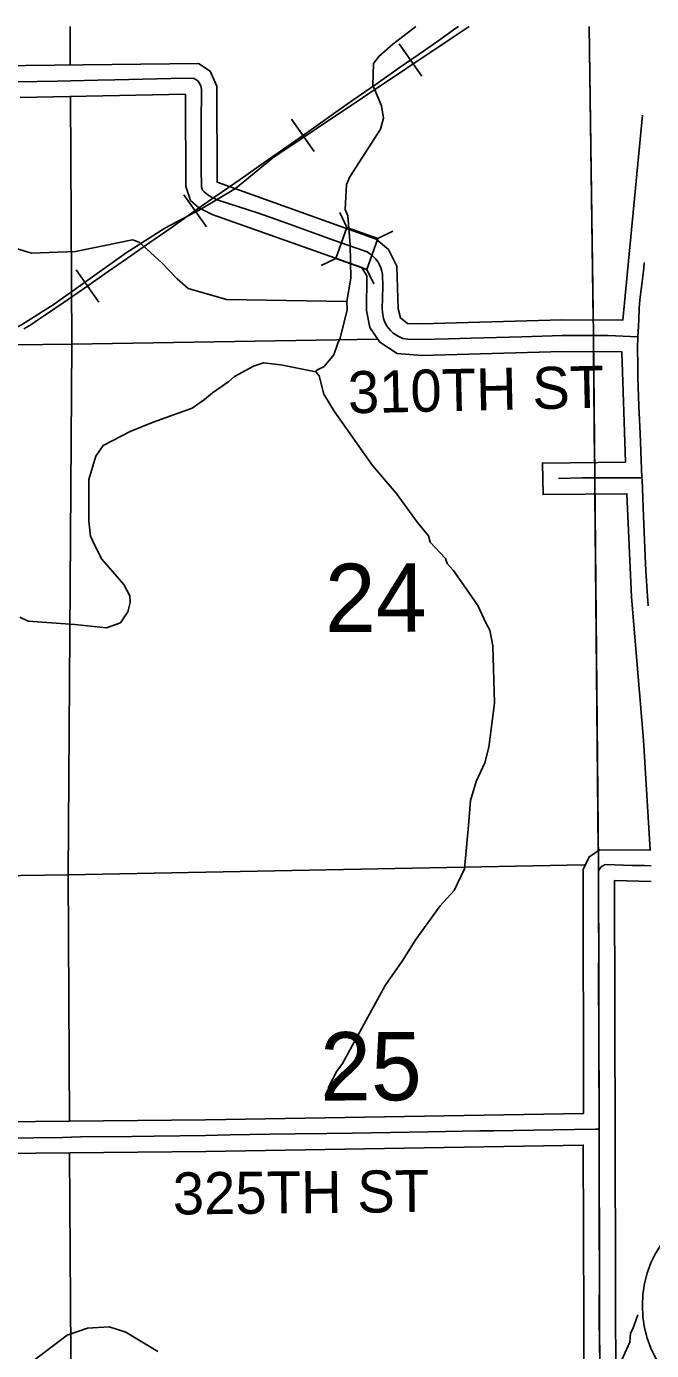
# Model space of a CAD drawing. Extents: x 10133 to 81668, y 7924 to 11018.
# Drawn here: x 12044.1 to 12222.4, y 9217.2 to 9594.9 of the extents above; entities that cross this region are included whole.
import ezdxf

# ---------------------------------------------------------------- set-up
doc = ezdxf.new("R2010")
doc.units = 0
for name, color, linetype in [('tdCoCityStreetMinor', 7, 'Continuous'), ('tdCoHydroRiver', 7, 'Continuous'), ('tdCoPriNonDiv', 7, 'Continuous'), ('tdCoRRCL', 7, 'Continuous'), ('tdCoRROwnerTxt', 7, 'Continuous'), ('tdCoShieldCoRte', 7, 'Continuous'), ('tdCoShieldCoRteHrd', 7, 'Continuous'), ('tdCoShieldStRte', 7, 'Continuous'), ('tdCoStrucNonDivPri', 7, 'Continuous'), ('tdCoSurfConc', 7, 'Continuous'), ('tdCoTwpNameTxt', 7, 'Continuous')]:
    doc.layers.add(name, color=color, linetype=linetype)

msp = doc.modelspace()

# ---------------------------------------------------------------- linework, layer by layer
at = {"layer": 'tdCoCityStreetMinor'}
for points in [[(12041.27, 9579.08), (12052.91, 9579.33), (12064.41, 9579.55), (12069.26, 9579.67), (12085.22, 9580.02), (12091.68, 9580.12), (12092.35, 9579.82), (12092.96, 9579.38), (12093.48, 9578.73), (12093.85, 9577.9), (12094, 9577.06), (12093.95, 9567.09), (12093.95, 9554.27), (12094.02, 9549.29), (12094.12, 9548.82), (12094.34, 9548.18), (12094.76, 9547.69), (12095.8, 9546.85), (12096.88, 9546.21), (12098.78, 9545.39), (12109.98, 9541.72), (12116.98, 9539.23), (12131.7, 9533.98), (12137.94, 9531.73), (12141.25, 9530.6), (12142.58, 9529.64), (12143.69, 9528.62), (12144.4, 9527.64), (12144.72, 9527.12), (12145.17, 9526.06), (12145.49, 9525.1), (12145.64, 9524.16), (12145.71, 9520.73), (12145.59, 9514.25), (12145.71, 9512.74), (12145.91, 9511.58), (12146.25, 9510.7), (12146.97, 9509.31), (12147.91, 9508.16), (12148.62, 9507.51), (12148.7, 9507.46), (12150.08, 9506.53), (12151.48, 9505.86), (12152.84, 9505.66), (12156.78, 9505.57), (12164.43, 9505.79), (12170.99, 9505.96), (12185.41, 9506.4), (12196.91, 9506.73), (12203.67, 9506.75), (12205.8, 9506.76), (12210.03, 9506.77), (12218.48, 9506.38)], [(12218.48, 9506.38), (12218.49, 9506.51), (12218.64, 9509.36), (12218.73, 9511.43), (12218.86, 9514.52), (12219.04, 9516.96), (12219.41, 9519.88), (12219.74, 9522.06), (12220.11, 9525.06), (12220.26, 9527.28), (12220.3, 9527.59)], [(12219.66, 9466.16), (12219.3, 9473.72), (12219.12, 9478.76), (12218.76, 9486.62), (12218.52, 9494.87), (12218.46, 9498.08), (12218.43, 9503.33), (12218.48, 9506.38)], [(12195.86, 9465.99), (12202.65, 9466.16), (12206.19, 9466.15), (12217.81, 9466.11), (12219.66, 9466.16)], [(12221.42, 9429.68), (12221.22, 9432.42), (12220.8, 9439.65), (12220.47, 9445.98), (12220.14, 9455.19), (12219.81, 9463.04), (12219.69, 9465.62), (12219.66, 9466.16)], [(12207.44, 9280.3), (12207.45, 9284.05), (12207.45, 9286.02), (12207.4, 9298.2), (12207.38, 9309.25), (12207.3, 9321.58), (12207.35, 9334.03), (12207.3, 9344.27), (12207.3, 9353.72), (12207.3, 9353.74), (12207.39, 9354.12), (12207.54, 9354.49), (12207.75, 9354.83), (12208, 9355.13), (12208.31, 9355.39), (12208.65, 9355.6), (12209.01, 9355.74), (12209.4, 9355.83), (12217, 9355.59), (12220.35, 9355.51), (12222.26, 9355.46)], [(12037.68, 9277.76), (12054.37, 9277.99), (12059.48, 9278.11), (12074.17, 9278.28), (12080.49, 9278.36), (12095.18, 9278.5), (12102.19, 9278.68), (12113.46, 9278.87), (12120.73, 9278.97), (12129.73, 9279.07), (12137.06, 9279.22), (12153.36, 9279.46), (12158.76, 9279.56), (12173.41, 9279.83), (12177.43, 9279.83), (12194.35, 9280.16), (12206.4, 9280.35), (12207.44, 9280.3)], [(12207.58, 9216.6), (12207.5, 9229.13), (12207.55, 9236.97), (12207.6, 9240), (12207.5, 9251.49), (12207.5, 9262.02), (12207.43, 9274.13), (12207.44, 9280.3)]]:
    msp.add_lwpolyline(points, dxfattribs=at)
at = {"layer": 'tdCoHydroRiver'}
for points in [[(12155.11, 9594.91), (12154.7, 9594.48), (12148.63, 9589.87), (12144.66, 9586.48), (12143.05, 9584.32), (12142.92, 9578.16), (12145.4, 9572.29), (12145.93, 9568.75), (12145.04, 9565.65), (12136.29, 9551.99), (12135.39, 9549.85), (12135.04, 9542.74), (12135.79, 9540.86), (12136.41, 9532.58), (12136.58, 9523.11), (12135.52, 9516.46)], [(12135.52, 9516.46), (12101.18, 9517.02), (12090.23, 9520.13), (12087.1, 9522.92), (12082.76, 9527.34), (12076.25, 9533.38), (12074.35, 9534.05), (12058.07, 9530.68), (12045.53, 9530.21), (12039.58, 9532), (12027.4, 9537.69), (12015.28, 9540.08), (11977.33, 9543.18), (11962.37, 9545.51), (11944.27, 9551.57)], [(12135.52, 9516.46), (12135.56, 9514.09), (12133.58, 9506.01), (12132.9, 9504.57), (12131.77, 9501.24), (12128.99, 9497.87), (12126.88, 9496.89), (12126.65, 9496.41)], [(12126.65, 9496.41), (12116.67, 9498.36), (12111.69, 9498.98), (12108.86, 9497.98), (12103.47, 9495.04), (12101.84, 9493.59), (12097.16, 9490.42), (12094.83, 9488.49), (12091.32, 9486.06), (12080.27, 9482.07), (12073.69, 9479.34), (12065.94, 9475.41), (12063.87, 9472.29), (12061.86, 9465.63), (12061.84, 9453.79), (12062.39, 9449.53), (12063.87, 9446.25), (12065.59, 9442.96), (12071.87, 9435.74), (12073.59, 9432.45), (12073.63, 9430.56), (12072.96, 9427.94), (12070.89, 9424.83), (12066.89, 9423.33), (12057.88, 9424.35), (12044.6, 9425.29), (12042.21, 9426.43)], [(12130.14, 9292.12), (12132.65, 9296.9), (12134.27, 9299.06), (12146.42, 9321.3), (12151.26, 9328.26), (12155.17, 9334.49), (12162.1, 9344.09), (12166.05, 9348.42), (12169.01, 9354.63), (12170.21, 9366.97), (12170.79, 9374.08), (12172.35, 9379.56), (12174.86, 9384.81), (12175.96, 9389.33), (12177.62, 9401.91), (12177.09, 9418.24), (12176.3, 9422.72), (12175.08, 9424.83), (12172.86, 9429.76), (12168.72, 9435.61), (12165.81, 9439.82), (12164.11, 9441.68), (12163.61, 9443.09), (12159.27, 9447.75), (12158.76, 9449.64), (12155.61, 9453.37), (12149.54, 9461.78), (12142.77, 9469.71), (12131.83, 9485.14), (12128.9, 9490.06), (12127.62, 9495.24), (12126.65, 9496.41)], [(12081.55, 9216.88), (12072.45, 9222.39), (12067.68, 9223.96), (12061.53, 9223.61), (12055.65, 9221.61), (12045.14, 9213.61)], [(12218.49, 9227.41), (12217.11, 9223.38), (12216.42, 9222.18), (12216.23, 9219.57), (12213.95, 9214.56), (12213.05, 9211.94), (12212.14, 9209.79), (12209.59, 9206.9), (12202.34, 9202.03), (12200.03, 9198.91), (12196.59, 9192.93), (12191.51, 9185.97), (12186.6, 9182.33), (12180.5, 9179.14), (12174.61, 9177.61), (12162.09, 9175.96), (12152.36, 9176.97), (12139.58, 9176.73), (12126.72, 9181), (12112.21, 9184.52), (12107.44, 9186.33)]]:
    msp.add_lwpolyline(points, dxfattribs=at)
at = {"layer": 'tdCoPriNonDiv'}
for points in [[(11945.48, 9594.91), (11941.74, 9584.93), (11945.05, 9582.64), (12093.14, 9584.37), (12096.46, 9582.2), (12098.43, 9577.84), (12098.5, 9550.47), (12143.88, 9534.24), (12147.33, 9531.26), (12149.76, 9526.52), (12150.09, 9514.39), (12150.75, 9511.79), (12152.8, 9510.22), (12156.77, 9510.07)], [(11978.62, 9281.84), (12095.11, 9283), (12202.95, 9284.8), (12202.86, 9354.4), (12204.58, 9358.05), (12207.67, 9360.04), (12222.02, 9359.96), (12220.06, 9391.28), (12216.73, 9432.09), (12215.36, 9461.62), (12191.48, 9461.38), (12191.25, 9470.37), (12214.94, 9470.62), (12213.94, 9502.09), (12196.98, 9502.23), (12156.91, 9501.07), (12149.86, 9501.66), (12144.9, 9504.81), (12142.06, 9509.07), (12141.1, 9513.88), (12141.15, 9523.76), (12139.74, 9526.14), (12097.01, 9541.26), (12093.23, 9543.15), (12090.92, 9545.27), (12089.52, 9549.22), (12089.49, 9575.58), (12042.25, 9574.6)], [(12156.77, 9510.07), (12196.78, 9511.22), (12214.21, 9511.08), (12219.82, 9569.56)], [(12222.27, 9351.02), (12211.8, 9351.25), (12212.17, 9201.66), (12211.22, 9057.76), (12221.68, 9057.59)], [(12203.18, 9201.65), (12202.93, 9275.8), (12095.23, 9274), (11978.74, 9272.85)]]:
    msp.add_lwpolyline(points, dxfattribs=at)
at = {"layer": 'tdCoRRCL'}
for p, q in [((12165.55, 9591.63), (12170.41, 9594.91)), ((12156.85, 9580.69), (12150.44, 9589.93)), ((12126.14, 9559.21), (12119.69, 9568.43)), ((12095.43, 9537.72), (12088.96, 9546.92)), ((12064.69, 9516.23), (12058.23, 9525.44))]:
    msp.add_line(p, q, dxfattribs=at)
for points in [[(12043.32, 9508.68), (12045.3, 9509.84), (12046.97, 9510.96), (12048.65, 9512.08), (12054.5, 9516.07), (12060.36, 9520.06), (12067.37, 9524.97), (12072.87, 9528.83), (12079.24, 9533.25), (12085.61, 9537.68), (12091.86, 9542.08), (12098.11, 9546.48), (12105.01, 9551.3), (12111.91, 9556.12), (12118.99, 9561.07), (12126.07, 9566.03), (12131.63, 9569.94), (12137.2, 9573.85), (12143.82, 9578.47), (12150.45, 9583.09), (12154.05, 9585.59), (12157.64, 9588.09), (12162.1, 9591.24), (12166.55, 9594.38), (12167.29, 9594.91)], [(11853.85, 9424.76), (11955.16, 9464.46), (12042.66, 9509.8), (12052.01, 9515.67), (12061.58, 9522.5), (12072.55, 9530.3), (12083.53, 9537.39), (12093.84, 9542.81), (12103.67, 9548.69), (12114.38, 9557.43), (12165.55, 9591.63)]]:
    msp.add_lwpolyline(points, dxfattribs=at)
at = {"layer": 'tdCoShieldCoRte'}
for points in [[(12133.48, 9541.83), (12135.49, 9537.59), (12144.34, 9534.45)], [(12128.12, 9526.73), (12132.35, 9528.75), (12135.49, 9537.59)], [(12148.57, 9536.47), (12144.34, 9534.45), (12141.2, 9525.61)], [(12143.17, 9521.46), (12141.2, 9525.61), (12132.35, 9528.75)]]:
    msp.add_lwpolyline(points, dxfattribs=at)
at = {"layer": 'tdCoShieldCoRteHrd'}
msp.add_line((12204.65, 9594.91), (12205.75, 9511.26), dxfattribs=at)
for points in [[(12205.85, 9502.26), (12206.16, 9470.65)], [(12206.24, 9461.65), (12207.22, 9359.81)]]:
    msp.add_lwpolyline(points, dxfattribs=at)
at = {"layer": 'tdCoStrucNonDivPri'}
for p, q in [((12056.53, 9594.91), (12056.58, 9583.89)), ((12205.75, 9511.26), (12204.65, 9594.91))]:
    msp.add_line(p, q, dxfattribs=at)
for points in [[(12056.63, 9574.9), (12057.01, 9504.3)], [(12023.85, 9503.93), (12057.01, 9504.3)], [(12057.01, 9504.3), (12055.93, 9352.87)], [(12057.01, 9504.3), (12144.12, 9505.74)], [(12205.85, 9502.26), (12206.16, 9470.65)], [(12206.24, 9461.65), (12207.22, 9359.81)], [(12022.22, 9352.42), (12055.93, 9352.87)], [(12055.93, 9352.87), (12203.26, 9355.77)], [(12055.93, 9352.87), (12056.33, 9282.51)], [(12056.38, 9273.51), (12056.79, 9202.66)]]:
    msp.add_lwpolyline(points, dxfattribs=at)
at = {"layer": 'tdCoSurfConc'}
msp.add_circle((12251.05, 9230), 31.27, dxfattribs=at)
at = {"layer": 'tdCoTwpNameTxt'}
msp.add_lwpolyline([(12204.65, 9594.91), (12205.81, 9506.76), (12207.26, 9355.85), (12207.65, 9199.23), (12206.71, 9053.29), (12058.44, 9052.45), (12055.44, 9052.43), (11906.7, 9050.03), (11903.62, 9049.96), (11751.72, 9046.27), (11602.3, 9041.92), (11599.58, 9041.89), (11448.66, 9038.75), (11287.47, 9032.68), (11137.48, 9029.42), (10987.91, 9025.85), (10954.88, 9025.06)], dxfattribs=at)

# ---------------------------------------------------------------- texts
at = {"layer": 'tdCoRROwnerTxt'}
for s, p in [('24', (12129.25, 9422.12)), ('25', (12127.89, 9288.49))]:
    msp.add_text(s, height=19.5, rotation=0.2315, dxfattribs=at).set_placement(p)
at = {"layer": 'tdCoShieldStRte'}
for s, rotation, p in [('310TH ST', 1.2884, (12135.9, 9484.52)), ('325TH ST', 0.5799, (12085.88, 9255.98))]:
    msp.add_text(s, height=12, rotation=rotation, dxfattribs=at).set_placement(p)

doc.saveas('drawing.dxf')
